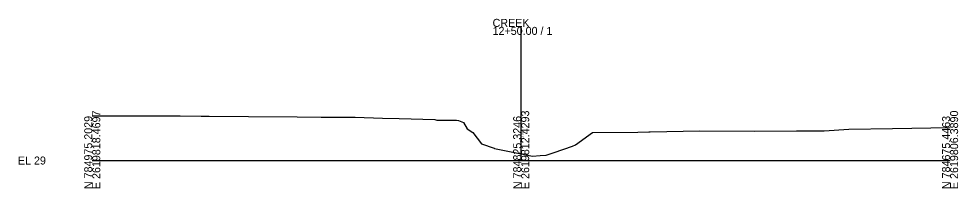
# Model space of a CAD drawing. Extents: x -26 to 303, y -10 to 5021.
# Drawn here: x -25.7 to 302.8, y 1990.3 to 2049.6 of the extents above; entities that cross this region are included whole.
import ezdxf

# ---------------------------------------------------------------- set-up
doc = ezdxf.new("R2010")
doc.units = 0
for name, color, linetype in [('RD_GPK_XS_Cell', 7, 'Continuous'), ('RD_XS_ExGround', 7, 'Continuous'), ('RD_XS_TX_Elev_EX', 7, 'Continuous')]:
    doc.layers.add(name, color=color, linetype=linetype)

msp = doc.modelspace()

# ---------------------------------------------------------------- linework, layer by layer
at = {"layer": 'RD_GPK_XS_Cell'}
for p, q in [((150, 2000), (150, 2046.76)), ((0, 2000), (150, 2000)), ((150, 2000), (300, 2000))]:
    msp.add_line(p, q, dxfattribs=at)
at = {"layer": 'RD_XS_ExGround'}
for p, q in [((0, 2015.59), (0.88, 2015.59)), ((0.88, 2015.59), (12.98, 2015.58)), ((12.98, 2015.58), (30.73, 2015.58)), ((30.73, 2015.58), (38.09, 2015.52)), ((38.09, 2015.52), (40.84, 2015.5)), ((40.84, 2015.5), (54.66, 2015.4)), ((54.66, 2015.4), (71.69, 2015.28)), ((71.69, 2015.28), (80.06, 2015.22)), ((80.06, 2015.22), (91.93, 2015.14)), ((91.93, 2015.14), (101.45, 2014.84)), ((101.45, 2014.84), (107.38, 2014.68)), ((107.38, 2014.68), (119.85, 2014.31)), ((119.85, 2014.31), (120.46, 2014.11)), ((120.46, 2014.11), (127.36, 2014.17)), ((127.36, 2014.17), (128.09, 2014)), ((128.09, 2014), (129.85, 2013.3)), ((129.85, 2013.3), (131.09, 2011.04)), ((131.09, 2011.04), (133.12, 2009.79)), ((255.92, 2010.44), (264.61, 2011.01)), ((264.61, 2011.01), (279.89, 2011.18)), ((279.89, 2011.18), (300, 2011.55)), ((133.12, 2009.79), (136.17, 2005.84)), ((169.01, 2005.49), (174.96, 2009.76)), ((174.96, 2009.76), (190.8, 2009.91)), ((190.8, 2009.91), (194.61, 2010.05)), ((194.61, 2010.05), (195.09, 2010.06)), ((195.09, 2010.06), (212.5, 2010.36)), ((212.5, 2010.36), (231.61, 2010.25)), ((231.61, 2010.25), (246.31, 2010.41)), ((246.31, 2010.41), (255.92, 2010.44)), ((136.17, 2005.84), (140.59, 2004.37)), ((140.59, 2004.37), (140.7, 2004.22)), ((140.7, 2004.22), (150, 2002.31)), ((161.54, 2002.8), (167.95, 2005.03)), ((167.95, 2005.03), (169.01, 2005.49)), ((150, 2002.31), (153.98, 2001.5)), ((153.98, 2001.5), (156.62, 2001.75)), ((156.62, 2001.75), (158.69, 2001.87)), ((158.69, 2001.87), (161.54, 2002.8))]:
    msp.add_line(p, q, dxfattribs=at)

# ---------------------------------------------------------------- texts
at = {"layer": 'RD_GPK_XS_Cell'}
for s, p in [('CREEK', (140, 2046.76)), ('12+50.00 / 1', (140, 2043.96)), ('EL 29', (-26, 1998.6))]:
    msp.add_text(s, height=2.8, dxfattribs=at).set_placement(p)
for s, p in [('E 2619818.4697', (2.8, 1990)), ('E 2619812.4293', (152.8, 1990)), ('E 2619806.3890', (302.8, 1990)), ('N 784975.2029', (0, 1990)), ('N 784825.3246', (150, 1990)), ('N 784675.4463', (300, 1990))]:
    msp.add_text(s, height=2.8, rotation=90, dxfattribs=at).set_placement(p)
at = {"layer": 'RD_XS_TX_Elev_EX'}
msp.add_text('31.31', height=0.8, rotation=90, dxfattribs=at).set_placement((150.7, 2007.31))

doc.saveas('drawing.dxf')
